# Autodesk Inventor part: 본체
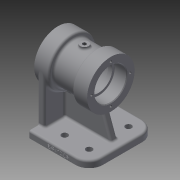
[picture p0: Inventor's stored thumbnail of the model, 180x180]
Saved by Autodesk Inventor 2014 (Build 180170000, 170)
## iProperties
Created: 2020-06
Part Number: 본체
Material: Generic
Document SubType Name: Modeling
Designer: kh
Density: 1 g/cm^3
Appearance: Default
Mass: 268.686 g
Surface Area: 641.471 cm^2
Volume: 268.686 cm^3
Author: kh
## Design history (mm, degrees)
sketch "Sketch1"
  geometry: L1 (-45, 49)-(45, 49); L2 (45, 49)-(45, -49); L3 (45, -49)-(-45, -49); L4 (-45, -49)-(-45, 49); L5 (-45, 49)-(45, -49); L6 (45, 49)-(-45, -49); 1 further point
  constraints: 12 end point, 2 midpoint, 2 parallel, 1 horizontal, 1 perpendicular
  dimensions: "d0" = 90 distance of L2.end L3.end; "d1" = 98 distance of L1.end L2.end
extrude "Extrusion1" new body sketch "Sketch1" distance "d2" = 10; taper "d3" = 0 deg
sketch "Sketch3"
  geometry: L1 (-28, 80)-(50, 80); L2 (-28, 80)-(-28, 115); L3 (-28, 115)-(-6, 115); L4 (-6, 115)-(-6, 109); L5 (-6, 109)-(28, 109); L6 (28, 109)-(28, 115); L7 (28, 115)-(50, 115); L8 (50, 115)-(50, 80); L9 (-45, 0)-(45, 0) reference; L10 (45, 0)-(-45, 0) reference; L11 (-45, 0)-(45, 0) reference; 1 further point
  constraints: 16 end point, 6 perpendicular, 1 horizontal, 1 parallel
  dimensions: "d4" = 70 diameter of L3 L1; "d5" = 78 distance between parallel lines of L8 L2; "d6" = 70 diameter of L7 L1; "d7" = 58 diameter of L5 L1; "d8" = 22 distance of L2.end L3.end; "d9" = 22 distance of L6.end L7.end; "d10" = 80 distance between parallel lines of L9 L1; "d16" = 5 distance from line of L9.end L8
revolve "Revolution1" sketch "Sketch3" stored, may be unused: angle "d11" = 90 deg
sketch "Sketch4"
  geometry: L1 (45, 0)-(-45, 0) reference; L2 (45, 0)-(45, 10) reference; L3 (-45, 10)-(45, 10) reference; L4 (-45, 0)-(-45, 10) reference; L5 (-28, 45)-(-28, 115) reference; L6 (45, 10)-(45, 70.445); L7 (-11, 70.445)-(-33, 10); L8 (45, 10)-(-33, 10); L9 (45, 70.445)-(-11, 70.445); 5 further points; 2 other entities
  constraints: 8 end point, 1 parallel, 1 perpendicular, 1 point on line, 4 other
extrude "Extrusion2" join sketch "Sketch4" stored distance "d17" = 10; taper "d18" = 0 deg
sketch "Sketch5"
  geometry: L1 (0, 0)-(0, 98) reference; L2 (10, 44)-(10, 0) reference; L3 (45.359, 44)-(10, 44) reference; L4 (10, 98)-(10, 54) reference; L5 (10, 84)-(80.327, 84); L6 (10, 14)-(80, 14); L7 (10, 84)-(10, 14); C1 r 35 at (80, 49) reference; A1 r 35 centre (80, 49) between (45.359, 44) and (80, 14) reference; 3 further points
  constraints: 6 end point, 2 midpoint, 2 point on line, 2 tangent, 1 horizontal alignment, 1 parallel, 1 point on circle
  dimensions: "d21" = 70 distance between parallel lines of L6 L5 (derived)
extrude "Extrusion3" join sketch "Sketch5" distance "d22" = 10; taper "d23" = 0 deg
mirror "Mirror1"
sketch "Sketch6"
  geometry: L1 (50, 45)-(50, 115) reference; L2 (-28, 45)-(-28, 115) reference; L3 (50, 80)-(-28, 80); L4 (50, 103.5)-(32.3, 103.5); L5 (32, 103.2)-(32, 100); L6 (32, 100)-(26, 100); L7 (26, 100)-(26, 100); L8 (23, 103)-(-1, 103); L9 (-4, 100)-(-4, 100); L10 (-4, 100)-(-10, 100); L11 (-10, 100)-(-10, 103.2); L12 (-10.3, 103.5)-(-28, 103.5); L13 (-28, 103.5)-(-28, 80); L14 (50, 103.5)-(50, 80); A1 r 3 centre (23, 100) between (26, 100) and (23, 103); A2 r 3 centre (-1, 100) between (-1, 103) and (-4, 100); A3 r 0.3 centre (32.3, 103.2) between (32.3, 103.5) and (32, 103.2); A4 r 0.3 centre (-10.3, 103.2) between (-10, 103.2) and (-10.3, 103.5); 3 further points
  constraints: 24 end point, 8 parallel, 8 point on circle, 8 tangent, 6 point on line, 4 centre point, 2 equal radius, 2 midpoint, 2 perpendicular, 1 collinear
  dimensions: "d24" = 47 diameter of L4 L3; "d25" = 46 diameter of L8 L3; "d26" = 47 diameter of L12 L3; "d27" = 6 distance between parallel lines of L7 L5; "d29" = 30 distance between parallel lines of L9 L7; "d30" = 18 distance of L4.start point (32, 103.5); "d31" = 18 distance of point (-10, 103.5) L12.end; "d32" = 3 radius of A1; "d33" = 0.3 radius of A3; "d34" = 40 diameter of L6 L3; "d35" = 40 diameter of L10 L3
revolve "Revolution2" sketch "Sketch6" stored, may be unused: angle "d36" = 90 deg
sketch "Sketch7"
  geometry: C1 r 23.5 at (0, 0) reference; 2 further points
  dimensions: "d37" = 28.5 distance of point (28.5, 0) C1.centre
hole "Hole1" sketch "Sketch7" at (28.5, 0) diameter "d38" = 3.242; stored, may be unused: countersink angle "d42" = 90 deg, drill point angle "d44" = 118 deg; dims "d39" = 10, "d40" = 4, "d41" = 2, "d43" = 12
pattern_circular "Circular Pattern1" dims angle "d46" = 360 deg
workplane "Work Plane1"
mirror "Mirror2"
workplane "Work Plane2"
sketch "Sketch8"
  geometry: L1 (50, -35)-(50, 35) reference; C1 r 6 at (11, 0); 1 further point
  constraints: 1 centre point
  dimensions: "d49" = 12 diameter of C1; "d94" = 39 distance from line of L1 C1.centre
extrude "Extrusion4" join sketch "Sketch8" stored distance "d50" = 12 (= d49); taper "d51" = 0 deg
hole "Hole2" diameter "d54" = 5.188; stored, may be unused: countersink angle "d58" = 90 deg, drill point angle "d60" = 118 deg; dims "d52" = 10, "d53" = 10, "d55" = 10, "d56" = 4, "d57" = 2, "d59" = 12
fillet "Fillet1" dims "d61" = 20
sketch "Sketch9"
  geometry: L1 (-45, 49)-(-45, 35) reference; 5 further points
  constraints: 2 horizontal alignment, 1 vertical alignment
  dimensions: "d64" = 58 distance of point (-11, -29) point (-11, 29); "d65" = 36 distance of point (25, 29) point (-11, 29); "d66" = 36 distance of point (25, -29) point (-11, -29); "d67" = 70 distance from line of L1 point (25, 29); "d68" = 29 vertical distance of point (0, 0) point (-11, 29)
hole "Hole3" sketch "Sketch9" at (-11, 29), (-11, -29), (25, 29), (25, -29) diameter "d69" = 9; stored, may be unused: countersink angle "d73" = 90 deg, drill point angle "d75" = 0 deg; dims "d70" = 10, "d71" = 4, "d72" = 2, "d74" = 9
fillet "Fillet2" dims "d76" = 3
fillet "Fillet3" dims "d77" = 3
fillet "Fillet4" dims "d78" = 3
fillet "Fillet5" dims "d79" = 3
fillet "Fillet6" dims "d80" = 3
fillet "Fillet7" dims "d81" = 3
fillet "Fillet8" dims "d82" = 3
fillet "Fillet9" dims "d83" = 3
fillet "Fillet10" dims "d84" = 3
chamfer "Chamfer1" distance "d85" = 1; stored, may be unused: second distance "d86" = 2, angle "d87" = 45 deg
sketch "Sketch10"
  geometry: L1 (67, 0)-(0, 0) reference; L2 (-3, 7)-(-3, 0) reference; 2 further points
  constraints: 1 other
  dimensions: "d90" = 4 distance from line of L1 point (42, 4); "d91" = 45 distance from line of L2 point (42, 4)
emboss "Emboss1" sketch "Sketch10" dims "d0" = 90, "d1" = 98, "d92" = 0.5, "d93" = 0
body "Solid1"
node "Projected Loop1"
node "Projected Loop2"
node "Projected Loop3"
node "Projected Loop4"
other parameters: "d48" = -112
